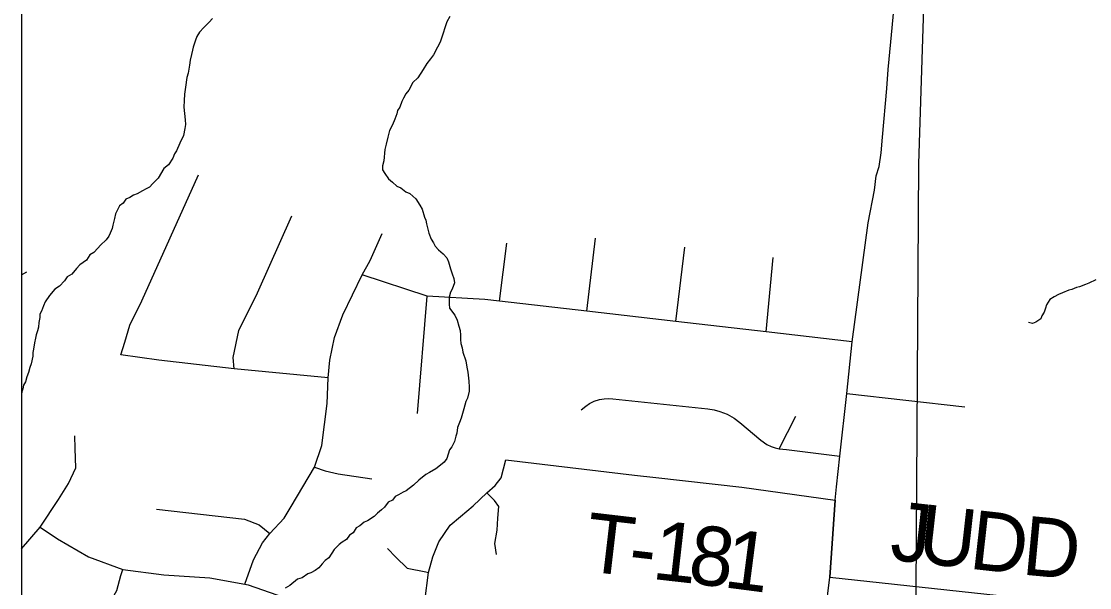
# Model space of a CAD drawing. Extents: x 0 to 34, y 0 to 22.
# Drawn here: x 2.1 to 3.128, y 15.409 to 15.954 of the extents above; entities that cross this region are included whole.
import ezdxf

# ---------------------------------------------------------------- set-up
doc = ezdxf.new("R2010")
doc.units = 0
for name, color, linetype in [('GM_X_Corporation', 7, 'Continuous'), ('GM_X_County_Road', 7, 'Continuous'), ('GM_X_Minor_River', 7, 'Continuous'), ('GM_X_Rail_Line', 7, 'Continuous'), ('GM_X_Township_Road', 7, 'Continuous'), ('GM_X_Township_Road_Text', 7, 'Continuous'), ('SH_Data', 7, 'Continuous')]:
    doc.layers.add(name, color=color, linetype=linetype)

msp = doc.modelspace()

# ---------------------------------------------------------------- linework, layer by layer
at = {"layer": 'GM_X_Corporation'}
msp.add_lwpolyline([(3.7872, 20.088), (2.9719, 18.1533), (2.8909, 17.9612), (2.886, 17.9497), (2.8709, 17.914), (2.8255, 17.8068), (2.811, 17.7726), (2.7544, 17.639), (2.225, 16.3897), (2.1, 16.0934), (2.1, 14.8365)], dxfattribs=at)
at = {"layer": 'GM_X_County_Road'}
msp.add_line((2.8777, 15.4194), (2.8829, 15.4935), dxfattribs=at)
for points in [[(2.8829, 15.4935), (2.8842, 15.5063), (2.8874, 15.5358), (2.894, 15.5961), (2.8994, 15.6456), (2.9147, 15.7602), (2.9206, 15.7916), (2.9222, 15.8054), (2.9252, 15.8145), (2.9273, 15.8275), (2.9285, 15.8425), (2.9327, 15.8893), (2.9339, 15.9077), (2.9364, 15.9344), (2.953, 16.1107)], [(2.8735, 15.3852), (2.8777, 15.4194)]]:
    msp.add_lwpolyline(points, dxfattribs=at)
at = {"layer": 'GM_X_Minor_River'}
for points in [[(2.284, 15.9566), (2.2806, 15.9532), (2.2755, 15.948), (2.2713, 15.9435), (2.2689, 15.9394), (2.2674, 15.936), (2.2653, 15.9292), (2.2645, 15.9262), (2.2637, 15.922), (2.2625, 15.9167), (2.2616, 15.9118), (2.2604, 15.9042), (2.2591, 15.9), (2.2578, 15.8906), (2.257, 15.8841), (2.2565, 15.878), (2.2564, 15.8716), (2.2577, 15.8594), (2.258, 15.8548), (2.2572, 15.851), (2.2559, 15.8442), (2.2524, 15.8367), (2.2492, 15.8295), (2.2473, 15.8265), (2.2457, 15.8224), (2.2414, 15.816), (2.2372, 15.8126), (2.2317, 15.8032), (2.2266, 15.798), (2.2232, 15.7946), (2.2201, 15.7928), (2.2166, 15.7909), (2.2113, 15.788), (2.2078, 15.7869), (2.2044, 15.7847), (2.2005, 15.7829), (2.1978, 15.7791), (2.1943, 15.7765), (2.1904, 15.769), (2.1896, 15.7644), (2.188, 15.758), (2.1875, 15.7546), (2.1855, 15.7504), (2.184, 15.7474), (2.1816, 15.7437), (2.1762, 15.7388), (2.1735, 15.7358), (2.1696, 15.7317), (2.1658, 15.7295), (2.1627, 15.7242), (2.1561, 15.7198), (2.153, 15.7164), (2.1484, 15.7108), (2.1442, 15.7082), (2.1414, 15.7045), (2.1368, 15.6992), (2.1322, 15.6963), (2.1271, 15.6903), (2.1228, 15.6843), (2.1213, 15.6805), (2.1193, 15.6752), (2.1177, 15.6722), (2.1177, 15.6692)], [(2.5122, 15.9587), (2.5094, 15.9534), (2.5074, 15.9478), (2.5058, 15.9425), (2.503, 15.9341), (2.5003, 15.9293), (2.4964, 15.9217), (2.4936, 15.918), (2.4901, 15.9135), (2.4866, 15.9078), (2.4815, 15.8996), (2.4765, 15.8951), (2.4726, 15.8879), (2.4699, 15.8842), (2.4675, 15.88), (2.466, 15.877), (2.464, 15.8714), (2.462, 15.8684), (2.4612, 15.8649), (2.4592, 15.86), (2.4572, 15.8544), (2.4541, 15.8491), (2.4525, 15.8427)], [(2.4525, 15.8427), (2.4508, 15.8359), (2.4496, 15.8306), (2.4487, 15.8199), (2.4474, 15.815), (2.4474, 15.8112), (2.4496, 15.8078), (2.4533, 15.8024), (2.4571, 15.7993), (2.4612, 15.7954), (2.4649, 15.7938), (2.4698, 15.7899), (2.4736, 15.7883), (2.4766, 15.786), (2.4796, 15.7833), (2.4833, 15.7771), (2.4855, 15.7733), (2.4877, 15.7657), (2.4891, 15.7626), (2.4898, 15.7592), (2.492, 15.7504), (2.4942, 15.7446), (2.4964, 15.7408), (2.4982, 15.7377), (2.5012, 15.7343), (2.5057, 15.7304), (2.5094, 15.7265), (2.5109, 15.7227), (2.5127, 15.7158), (2.5145, 15.7112), (2.5159, 15.7066), (2.5166, 15.7024), (2.5143, 15.6964), (2.5127, 15.6934), (2.5115, 15.6888), (2.5114, 15.682), (2.512, 15.6782), (2.5169, 15.6713), (2.5191, 15.6667), (2.5209, 15.6609), (2.522, 15.6567), (2.5223, 15.6522), (2.5226, 15.648), (2.5229, 15.6442), (2.524, 15.64), (2.5246, 15.6358), (2.5275, 15.6274), (2.5286, 15.6213), (2.5296, 15.6167), (2.5306, 15.6079), (2.5309, 15.6022), (2.5309, 15.5984), (2.5292, 15.5916), (2.5276, 15.5882), (2.5256, 15.5814), (2.5232, 15.5723), (2.5216, 15.5682), (2.5196, 15.5633), (2.5188, 15.558), (2.518, 15.5549), (2.5167, 15.55), (2.514, 15.5447), (2.512, 15.5417), (2.5092, 15.5334), (2.5069, 15.53), (2.5031, 15.5271), (2.4988, 15.5237), (2.4927, 15.52), (2.4892, 15.5182), (2.4823, 15.5126), (2.4773, 15.5077), (2.4703, 15.5025), (2.4673, 15.5011), (2.4627, 15.4985), (2.4596, 15.497), (2.4569, 15.4933), (2.453, 15.4914), (2.4495, 15.4866), (2.4464, 15.484), (2.4426, 15.481), (2.4395, 15.4776), (2.433, 15.4735), (2.4299, 15.4721), (2.4257, 15.4687), (2.4222, 15.4669), (2.4191, 15.462), (2.4156, 15.4598), (2.4129, 15.4557), (2.4087, 15.4531), (2.4056, 15.4508), (2.4009, 15.446), (2.3959, 15.4381), (2.3924, 15.4355), (2.3893, 15.4321), (2.3862, 15.4284), (2.3827, 15.4258), (2.3785, 15.4236), (2.3755, 15.4225), (2.3701, 15.4188), (2.3655, 15.4173), (2.3582, 15.4114)], [(3.1337, 15.7053), (3.1268, 15.702), (3.1238, 15.7009), (3.118, 15.6987), (3.115, 15.698), (3.1107, 15.6962), (3.1077, 15.6955), (3.1016, 15.6929), (3.0977, 15.6911), (3.0935, 15.6889), (3.0893, 15.6863), (3.0862, 15.6814), (3.0854, 15.678), (3.0838, 15.6742), (3.0818, 15.6708), (3.0806, 15.6678), (3.076, 15.6645), (3.0726, 15.6634), (3.0688, 15.6642)], [(2.1177, 15.6692), (2.1168, 15.6642), (2.1164, 15.6597), (2.1155, 15.6563), (2.1143, 15.6525), (2.1135, 15.6491), (2.1127, 15.6449), (2.1118, 15.6388), (2.111, 15.6354), (2.1109, 15.632), (2.1093, 15.6244), (2.1081, 15.621), (2.1069, 15.6161), (2.1053, 15.612), (2.1041, 15.6071), (2.1021, 15.604), (2.1013, 15.6006), (2.1005, 15.5976), (2.1, 15.595)], [(2.3582, 15.4114), (2.3539, 15.4088)]]:
    msp.add_lwpolyline(points, dxfattribs=at)
at = {"layer": 'GM_X_Rail_Line'}
msp.add_lwpolyline([(2.7988, 17.139), (2.8205, 17.0146), (2.8367, 16.7553), (2.8621, 16.4782), (2.88, 16.3843), (2.946, 16.1063), (2.9681, 15.9775), (2.9632, 15.8168), (2.9604, 15.4067), (2.9714, 15.0477), (3.006, 14.6804), (3.0102, 14.5176), (3.0299, 14.3321), (3.0382, 14.2206), (3.0407, 14.1566), (3.0308, 14.1)], dxfattribs=at)
at = {"layer": 'GM_X_Township_Road'}
for p, q in [((2.644, 15.6753), (2.6523, 15.7456)), ((2.5601, 15.685), (2.567, 15.7407)), ((2.7295, 15.6654), (2.7382, 15.7369)), ((2.8166, 15.6553), (2.8233, 15.727)), ((2.1, 15.7102), (2.1051, 15.7129)), ((2.481, 15.5769), (2.4904, 15.6898)), ((2.894, 15.5961), (3.0075, 15.5831)), ((2.8291, 15.5428), (2.8451, 15.5742)), ((2.566, 15.5321), (2.6898, 15.5175)), ((2.8829, 15.4935), (2.8777, 15.4194))]:
    msp.add_line(p, q, dxfattribs=at)
for points in [[(2.3953, 15.6112), (2.3046, 15.6198), (2.2321, 15.628), (2.1956, 15.6333), (2.1996, 15.6455), (2.2042, 15.6616), (2.216, 15.6851), (2.2703, 15.8063)], [(2.3046, 15.6198), (2.3039, 15.6308), (2.3092, 15.6566), (2.3271, 15.693), (2.3603, 15.767)], [(2.3151, 15.4125), (2.3232, 15.4359), (2.332, 15.4525), (2.3391, 15.4613), (2.3529, 15.476), (2.3597, 15.4872), (2.3819, 15.5252), (2.389, 15.546), (2.3943, 15.5865), (2.3953, 15.6112), (2.3968, 15.628), (2.4011, 15.6498), (2.4093, 15.6716), (2.4279, 15.7102), (2.4354, 15.7241), (2.4472, 15.7498)], [(2.8994, 15.6456), (2.8166, 15.6553), (2.7295, 15.6654), (2.644, 15.6753), (2.5601, 15.685), (2.5458, 15.6863), (2.4904, 15.6898), (2.4279, 15.7102)], [(2.6387, 15.5804), (2.6429, 15.5838), (2.6466, 15.5864), (2.6509, 15.5885), (2.6561, 15.5902), (2.6606, 15.5909), (2.6651, 15.5912), (2.669, 15.5908), (2.7605, 15.5812), (2.7665, 15.5803), (2.7721, 15.5788), (2.7789, 15.5762), (2.7858, 15.5723), (2.7911, 15.5682), (2.8114, 15.5512), (2.8172, 15.547), (2.8213, 15.5451), (2.8252, 15.5437), (2.8291, 15.5428), (2.8325, 15.5425), (2.8362, 15.5421), (2.8874, 15.5358)], [(2.1, 15.4465), (2.1181, 15.4674), (2.1356, 15.4941), (2.1452, 15.5096), (2.1523, 15.5246), (2.1518, 15.543), (2.1515, 15.5552)], [(2.4883, 15.3961), (2.4916, 15.4237), (2.4957, 15.4388), (2.5017, 15.4533), (2.5125, 15.4693), (2.5225, 15.4776), (2.5345, 15.488), (2.5477, 15.5006), (2.5559, 15.5074), (2.5616, 15.5148), (2.566, 15.5321)], [(2.3819, 15.5252), (2.3923, 15.5217), (2.4049, 15.5189), (2.4371, 15.514)], [(2.6898, 15.5175), (2.7105, 15.5151), (2.793, 15.5058), (2.8829, 15.4935)], [(2.557, 15.4412), (2.5556, 15.4516), (2.5578, 15.4645), (2.5583, 15.476), (2.5593, 15.4872), (2.5552, 15.493), (2.5477, 15.5006)], [(2.2299, 15.4848), (2.3147, 15.4751), (2.3289, 15.4698), (2.3391, 15.4613)], [(2.1181, 15.4674), (2.1348, 15.4561), (2.1645, 15.4389), (2.1976, 15.4266), (2.2372, 15.4216), (2.2812, 15.4187), (2.3151, 15.4125), (2.3182, 15.4119), (2.3808, 15.3901), (2.4348, 15.3814), (2.4389, 15.3806), (2.4858, 15.3734)], [(2.4523, 15.4469), (2.4602, 15.4386), (2.4711, 15.428), (2.4891, 15.4246), (2.4916, 15.4237)], [(2.1594, 15.2406), (2.153, 15.2616), (2.1497, 15.2822), (2.1488, 15.2961), (2.1499, 15.3065), (2.1528, 15.3211), (2.1622, 15.3472), (2.1747, 15.3715), (2.1827, 15.3903), (2.1917, 15.4064), (2.1957, 15.421), (2.1976, 15.4266)], [(2.8777, 15.4194), (3.0526, 15.4004), (3.0789, 15.3973), (3.0941, 15.3956), (3.122, 15.3935), (3.1613, 15.3944), (3.2012, 15.3971), (3.2627, 15.4013), (3.3345, 15.404), (3.4142, 15.4085), (3.4451, 15.4103), (3.4629, 15.4118), (3.4785, 15.4129), (3.4903, 15.4133), (3.5128, 15.4146), (3.7177, 15.3992), (3.7519, 15.397), (3.766, 15.397), (3.784, 15.3976), (3.7936, 15.3981), (3.804, 15.3981), (3.814, 15.3987), (4.0031, 15.3877)]]:
    msp.add_lwpolyline(points, dxfattribs=at)
at = {"layer": 'SH_Data'}
msp.add_line((2.1, 20.9), (2.1, 14.1), dxfattribs=at)

# ---------------------------------------------------------------- texts
at = {"layer": 'GM_X_Township_Road_Text'}
for s, rotation, p in [('J', 353.5663, (2.9345, 15.4363)), ('U', 353.5645, (2.961, 15.4334)), ('T', 353.3184, (2.6404, 15.4254)), ('D', 353.5785, (3.0107, 15.4277)), ('D', 354.6233, (3.0615, 15.422)), ('1', 353.5317, (2.7057, 15.4178)), ('8', 353.3001, (2.7402, 15.4138)), ('1', 352.6252, (2.7745, 15.4098)), ('-', 353.4075, (2.6826, 15.4204))]:
    msp.add_text(s, height=0.0568, rotation=rotation, dxfattribs=at).set_placement(p)

doc.saveas('drawing.dxf')
